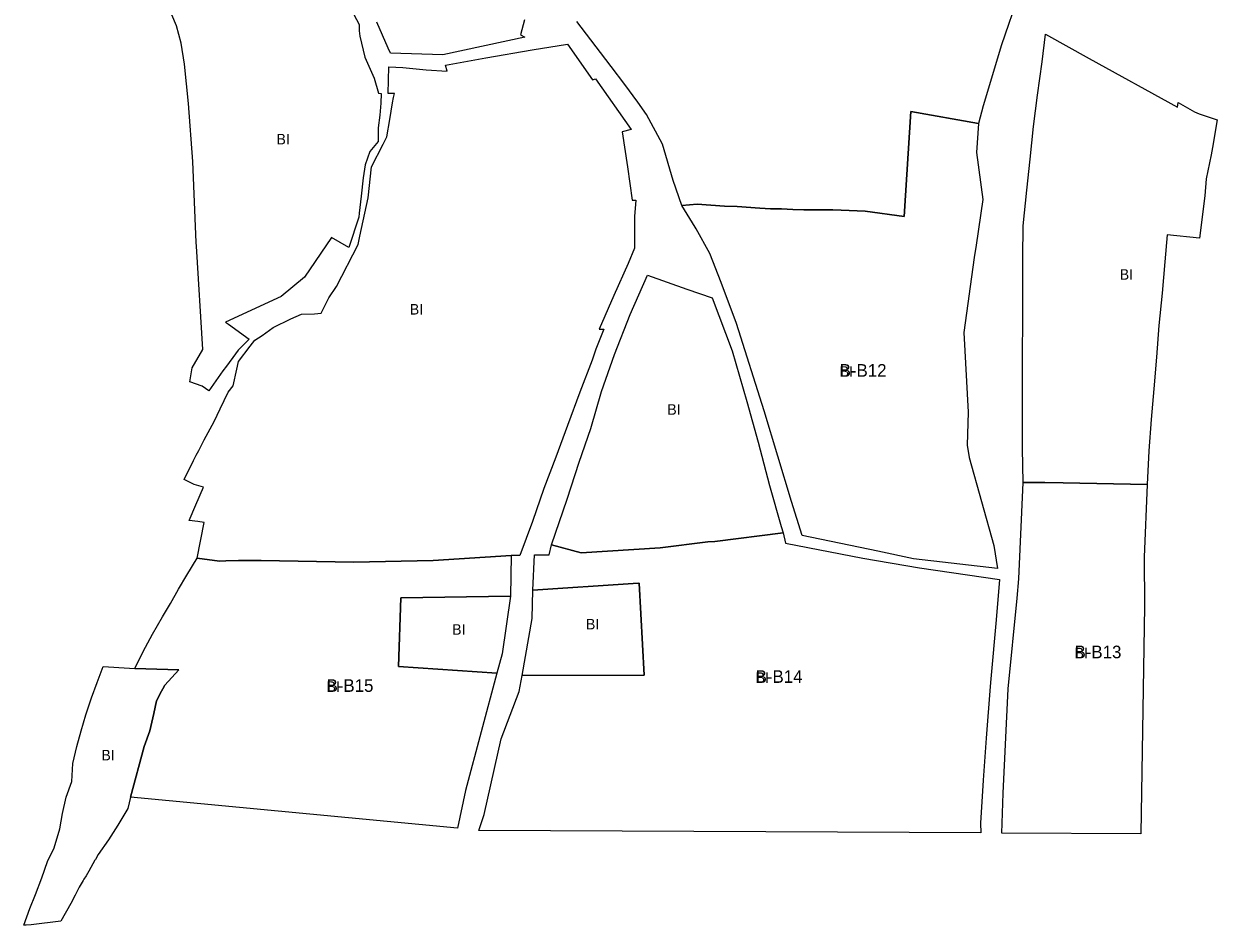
# Model space of a CAD drawing. Extents: x -532081 to -530154, y -1179372 to -1177675.
# Drawn here: x -530768 to -530200, y -1178869 to -1178440 of the extents above; entities that cross this region are included whole.
import ezdxf

# ---------------------------------------------------------------- set-up
doc = ezdxf.new("R2010")
doc.units = 0
for name, color, linetype in [('90040013', 7, 'Continuous'), ('90040023', 7, 'Continuous'), ('ID_navrh', 7, 'Continuous')]:
    doc.layers.add(name, color=color, linetype=linetype)

msp = doc.modelspace()

# ---------------------------------------------------------------- linework, layer by layer
at = {"layer": '90040013'}
for points in [[(-530294.09, -1178425.6), (-530302.58, -1178450.15), (-530311.3, -1178479.17), (-530313.46, -1178487.69), (-530345.7, -1178481.88), (-530348.85, -1178531.9), (-530367.4, -1178529.27), (-530378.77, -1178528.92), (-530382.79, -1178528.74), (-530396.61, -1178528.74), (-530401.86, -1178528.57), (-530407.29, -1178528.21), (-530412.53, -1178528.21), (-530417.61, -1178527.86), (-530428.28, -1178527.16), (-530434.4, -1178526.99), (-530447.35, -1178525.93), (-530454.6, -1178526.58), (-530458.81, -1178514.72), (-530463.83, -1178497.5), (-530471.42, -1178483.38), (-530475.67, -1178477.45), (-530481.77, -1178469.1), (-530488.24, -1178460.57), (-530493.42, -1178453.9), (-530504.6, -1178439.02)], [(-530612.05, -1178433.34), (-530608.21, -1178440.48), (-530608.18, -1178443.55), (-530607.87, -1178446.02), (-530605.52, -1178456.03), (-530601.11, -1178466.06), (-530599.03, -1178473.17), (-530597.81, -1178473.29), (-530597.93, -1178477.88), (-530598.45, -1178483.69), (-530599.24, -1178489.63), (-530599.16, -1178496.19), (-530603.2, -1178501), (-530605.34, -1178507.25), (-530606.34, -1178513.55), (-530607.3, -1178522.25), (-530608.19, -1178530.33), (-530608.36, -1178532.26), (-530613.18, -1178546.58), (-530621.43, -1178541.94), (-530634.3, -1178560.69), (-530645.36, -1178569.97), (-530671.83, -1178582.22), (-530670.5, -1178583.17), (-530660.62, -1178590.19), (-530665.84, -1178595.47), (-530667.06, -1178597.28), (-530671.4, -1178603.05), (-530673.08, -1178605.36), (-530679.72, -1178614.85), (-530682.98, -1178612.57), (-530688.81, -1178610.55), (-530687.76, -1178603.9), (-530682.64, -1178595.14), (-530685.65, -1178546.03), (-530685.77, -1178544.26), (-530687.34, -1178505.73), (-530689.52, -1178478.17), (-530691.4, -1178459.37), (-530692.96, -1178449.35), (-530695.14, -1178441.21), (-530697.33, -1178435.88)], [(-530529.57, -1178438.26), (-530531.53, -1178445.39), (-530529.4, -1178446.46), (-530568.43, -1178454.9), (-530593.27, -1178454.09), (-530594.39, -1178451.84), (-530599.84, -1178439.46)]]:
    msp.add_lwpolyline(points, dxfattribs=at)
for points in [[(-530260.74, -1178456.75), (-530218.69, -1178479.81), (-530218.45, -1178477.61), (-530210.63, -1178482.02), (-530208.43, -1178483), (-530199.89, -1178485.8), (-530202.08, -1178499), (-530202.68, -1178502.6), (-530205.07, -1178514.01), (-530205.67, -1178522.01), (-530208.21, -1178542.11), (-530223.69, -1178540.58), (-530224.78, -1178553.49), (-530226.09, -1178568.37), (-530227.62, -1178583.69), (-530228.71, -1178598.78), (-530230.02, -1178613.88), (-530231.32, -1178628.54), (-530232.47, -1178643.35), (-530233.15, -1178659.45), (-530273.21, -1178658.64), (-530281.84, -1178658.5), (-530292.22, -1178658.5), (-530292.49, -1178642.27), (-530292.54, -1178626.59), (-530292.54, -1178597.01), (-530292.43, -1178581.6), (-530292.43, -1178566.41), (-530292.32, -1178551.34), (-530292.18, -1178536.38), (-530290.43, -1178519.28), (-530288.95, -1178504.61), (-530287.25, -1178489.08), (-530285.34, -1178474.19), (-530283.22, -1178458.24), (-530281.52, -1178445.05)], [(-530509.15, -1178449.84), (-530497.23, -1178466.84), (-530495.8, -1178466.32), (-530478.81, -1178490.48), (-530483, -1178491.58), (-530480.58, -1178508.17), (-530478.37, -1178524.1), (-530476.61, -1178524.1), (-530477.27, -1178531.84), (-530477.27, -1178546.89), (-530480.14, -1178554.19), (-530486.97, -1178569.45), (-530493.99, -1178585.5), (-530491.74, -1178585.5), (-530495.57, -1178594.98), (-530497.37, -1178600.18), (-530503.22, -1178615.53), (-530509.08, -1178631.34), (-530514.7, -1178646.47), (-530520.33, -1178661.37), (-530525.73, -1178676.96), (-530531.81, -1178693.21), (-530535.89, -1178693.13), (-530573.04, -1178695.56), (-530610.99, -1178696.42), (-530654.81, -1178695.55), (-530665.65, -1178695.55), (-530671.66, -1178695.71), (-530674.76, -1178695.94), (-530685.35, -1178694.47), (-530682.08, -1178677.41), (-530685.01, -1178676.96), (-530689.14, -1178676.48), (-530686.03, -1178669.07), (-530682.26, -1178660.67), (-530686.8, -1178659.45), (-530691.61, -1178657.05), (-530687.12, -1178648.05), (-530685.82, -1178645.47), (-530684.57, -1178643.19), (-530682.08, -1178638.19), (-530677.31, -1178629.45), (-530674.41, -1178623.41), (-530670.67, -1178615.51), (-530668.18, -1178612.38), (-530666.48, -1178604.49), (-530665.75, -1178600.92), (-530660.05, -1178593.52), (-530657.85, -1178590.69), (-530654.47, -1178588.46), (-530649.14, -1178584.69), (-530640.8, -1178580.62), (-530635.7, -1178578.39), (-530629.48, -1178578.17), (-530626.4, -1178577.82), (-530622.64, -1178570.6), (-530619.02, -1178565.13), (-530608.76, -1178545.16), (-530607.89, -1178541.21), (-530603.94, -1178522.98), (-530602.35, -1178508.32), (-530596.89, -1178497.38), (-530595.14, -1178493.96), (-530593.71, -1178485.72), (-530592.4, -1178477.72), (-530591.85, -1178475.22), (-530591.44, -1178473.36), (-530594.51, -1178473.28), (-530594.11, -1178460.68), (-530587.43, -1178460.95), (-530576.36, -1178462.02), (-530566.35, -1178462.69), (-530567.12, -1178459.92), (-530547.93, -1178456.41), (-530525.84, -1178452.5)], [(-530464.9, -1178689.6), (-530502.51, -1178691.91), (-530516.7, -1178688.06), (-530509.22, -1178666.31), (-530503.46, -1178648.8), (-530497.92, -1178632.68), (-530492.88, -1178615.2), (-530486.79, -1178597.5), (-530479.23, -1178578.54), (-530471.04, -1178559.79), (-530452.35, -1178566.53), (-530440.16, -1178570.54), (-530430.71, -1178595.82), (-530423.78, -1178619.83), (-530418.36, -1178639.21), (-530412.88, -1178659.85), (-530407.41, -1178679.37), (-530406.46, -1178682.4), (-530439, -1178686.52), (-530442.26, -1178686.71)], [(-530472.61, -1178750.1), (-530530.73, -1178750.31), (-530525.84, -1178723.12), (-530525.53, -1178709.62), (-530477.76, -1178706.54), (-530475.12, -1178706.38), (-530475.03, -1178706.37)], [(-530540.24, -1178739.95), (-530542.7, -1178749.16), (-530589.5, -1178746.06), (-530588.46, -1178713.31), (-530536.18, -1178712.62)], [(-530766.78, -1178869.08), (-530767.83, -1178869.08), (-530765.03, -1178861.12), (-530762.23, -1178854.45), (-530759.31, -1178846.6), (-530756.51, -1178838.88), (-530753.43, -1178832.36), (-530750.79, -1178823.26), (-530749.51, -1178816), (-530747.64, -1178808.16), (-530744.95, -1178800.78), (-530744.6, -1178792.24), (-530742.62, -1178784.04), (-530740.61, -1178776.59), (-530738.39, -1178769.03), (-530735.64, -1178760.95), (-530732.9, -1178753.56), (-530730.16, -1178746), (-530717.59, -1178746.82), (-530715.09, -1178746.94), (-530694.01, -1178747.54), (-530700.68, -1178754.83), (-530701.62, -1178756.58), (-530702.25, -1178757.75), (-530704.72, -1178762.35), (-530705.92, -1178768.33), (-530707.82, -1178776.57), (-530710.56, -1178784.08), (-530717.06, -1178808.12), (-530718.28, -1178813.62), (-530723.06, -1178821.56), (-530727.56, -1178828.57), (-530732.47, -1178835.48), (-530733.79, -1178837.81), (-530734.02, -1178838.23), (-530736.9, -1178843.33), (-530738.25, -1178845.56), (-530739.24, -1178847.19), (-530739.63, -1178847.84), (-530741.57, -1178851.05), (-530742.18, -1178852.28), (-530743.47, -1178854.85), (-530745.42, -1178858.78), (-530750.21, -1178867.21), (-530764.33, -1178868.97)]]:
    msp.add_lwpolyline(points, close=True, dxfattribs=at)
at = {"layer": '90040023'}
for points in [[(-530314.6, -1178545.49), (-530315.45, -1178551.35), (-530320.45, -1178587.04), (-530318.45, -1178624.99), (-530318.85, -1178640.66), (-530317.94, -1178646.55), (-530306.15, -1178688.49), (-530304.49, -1178699.45), (-530344.33, -1178694.71), (-530361.33, -1178691.11), (-530397.45, -1178683.64), (-530402.49, -1178667.57), (-530415.53, -1178624.42), (-530428.57, -1178582.87), (-530435.97, -1178563.29), (-530441.32, -1178549.48), (-530447.8, -1178537.79), (-530448.34, -1178536.89), (-530454.6, -1178526.58), (-530447.35, -1178525.93), (-530434.4, -1178526.99), (-530428.28, -1178527.16), (-530417.61, -1178527.86), (-530412.53, -1178528.21), (-530407.29, -1178528.21), (-530401.86, -1178528.57), (-530396.61, -1178528.74), (-530382.79, -1178528.74), (-530378.77, -1178528.92), (-530367.4, -1178529.27), (-530348.85, -1178531.9), (-530345.7, -1178481.88), (-530313.46, -1178487.69), (-530314.45, -1178501.4), (-530311.47, -1178523.8)], [(-530294.25, -1178704.37), (-530292.22, -1178658.5), (-530281.84, -1178658.5), (-530273.21, -1178658.64), (-530233.15, -1178659.45), (-530234.61, -1178693.97), (-530234.42, -1178717.35), (-530236.14, -1178825.58), (-530302.35, -1178825.25), (-530301.79, -1178806.21), (-530299.39, -1178756.64), (-530295.06, -1178713.57)], [(-530312.42, -1178825.2), (-530551.35, -1178823.99), (-530548.82, -1178816.38), (-530540.72, -1178780.49), (-530532.11, -1178757.96), (-530530.73, -1178750.31), (-530472.61, -1178750.1), (-530475.03, -1178706.37), (-530475.12, -1178706.38), (-530477.76, -1178706.54), (-530525.53, -1178709.62), (-530524.76, -1178692.87), (-530517.85, -1178692.87), (-530516.7, -1178688.06), (-530502.51, -1178691.91), (-530464.9, -1178689.6), (-530442.26, -1178686.71), (-530439, -1178686.52), (-530406.46, -1178682.4), (-530405.33, -1178687.32), (-530368.5, -1178694.52), (-530341.5, -1178699.07), (-530303.49, -1178704.62), (-530305.13, -1178723.79), (-530307.54, -1178751.83), (-530307.84, -1178755.59), (-530309.78, -1178780.11), (-530311.28, -1178800.09), (-530312.55, -1178820.59)], [(-530561.48, -1178823.02), (-530717.06, -1178808.12), (-530710.56, -1178784.08), (-530707.82, -1178776.57), (-530705.92, -1178768.33), (-530704.72, -1178762.35), (-530702.25, -1178757.75), (-530701.62, -1178756.58), (-530700.68, -1178754.83), (-530694.01, -1178747.54), (-530715.09, -1178746.94), (-530711.04, -1178738.82), (-530706.63, -1178730.58), (-530701.82, -1178722.38), (-530698.07, -1178716.05), (-530694.24, -1178709.16), (-530690.3, -1178702.6), (-530685.35, -1178694.47), (-530674.76, -1178695.94), (-530671.66, -1178695.71), (-530665.65, -1178695.55), (-530654.81, -1178695.55), (-530610.99, -1178696.42), (-530573.04, -1178695.56), (-530535.89, -1178693.13), (-530536.18, -1178712.62), (-530588.46, -1178713.31), (-530589.5, -1178746.06), (-530542.7, -1178749.16), (-530557.63, -1178805.08)]]:
    msp.add_lwpolyline(points, close=True, dxfattribs=at)

# ---------------------------------------------------------------- texts
at = {"layer": '90040013'}
for rotation, p in [(0, (-530647.57, -1178497.56)), (360, (-530246.22, -1178561.95)), (360, (-530461.58, -1178626.19)), (0, (-530563.96, -1178730.89)), (360, (-530500.3, -1178728.34)), (360, (-530730.92, -1178790.69))]:
    msp.add_text('BI', height=5, rotation=rotation, dxfattribs=at).set_placement(p)
msp.add_text('BI', height=5, dxfattribs=at).set_placement((-530584.11, -1178578.54))
at = {"layer": '90040023'}
for rotation, p in [(360, (-530379.54, -1178608.11)), (0, (-530267.75, -1178742.08)), (0, (-530419.53, -1178753.8)), (360, (-530623.75, -1178758.08))]:
    msp.add_text('BI', height=5, rotation=rotation, dxfattribs=at).set_placement(p)
at = {"layer": 'ID_navrh'}
for s, rotation, p in [('B-B12', 360, (-530379.54, -1178608.11)), ('B-B13', 360, (-530267.75, -1178742.08)), ('B-B14', 360, (-530419.53, -1178753.8)), ('B-B15', 0, (-530623.75, -1178758.08))]:
    msp.add_text(s, height=6, rotation=rotation, dxfattribs=at).set_placement(p)

doc.saveas('drawing.dxf')
